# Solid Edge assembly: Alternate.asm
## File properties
Author: ptcarter
Template: Normal.asm
Last saved by: User
Revision: 62
Application: Solid Edge
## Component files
Body01.par
SideFlange01.asm
NutM15.par
SideFlange02.asm
Handle01.par
Valve01.asm
TopFlange01.asm
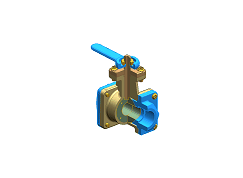
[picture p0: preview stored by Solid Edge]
